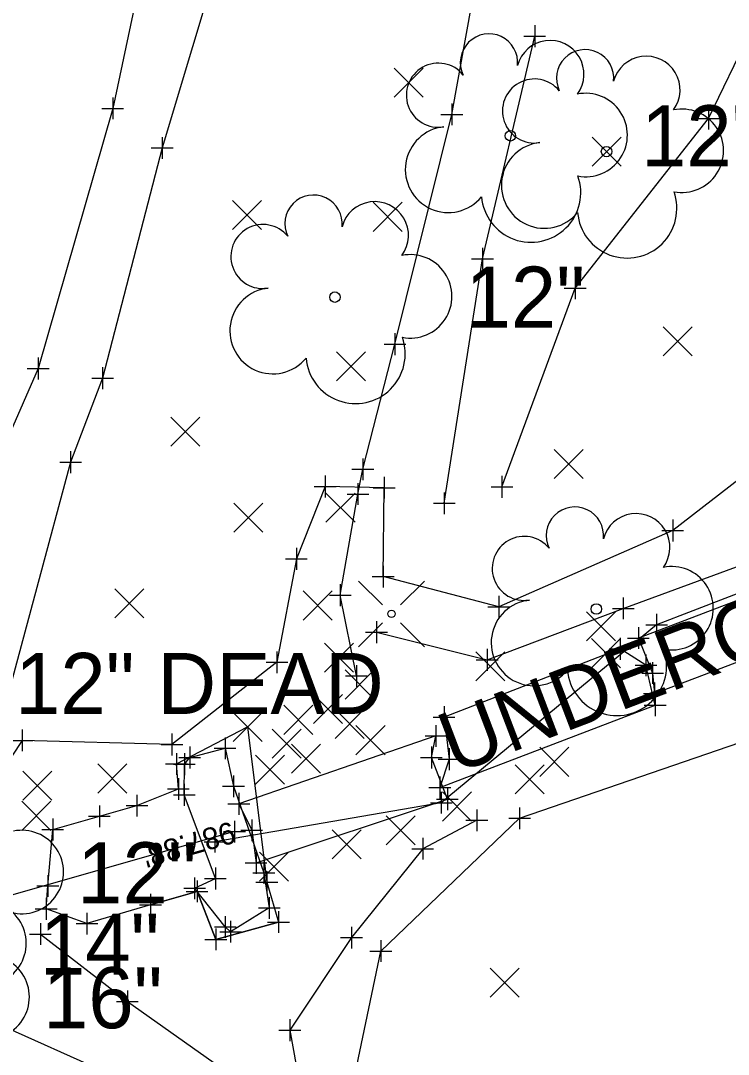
# Model space of a CAD drawing. Extents: x 160138 to 160780, y 488720 to 491073.
# Drawn here: x 160554.44 to 160586.95, y 489677.72 to 489725.18 of the extents above; entities that cross this region are included whole.
import ezdxf

# ---------------------------------------------------------------- set-up
doc = ezdxf.new("R2010")
doc.units = 0
for name, color, linetype in [('_CIVIL_CONSTRUCTION', 7, 'Continuous'), ('DR_X_Storm_Sewer', 7, 'Continuous'), ('GE_X_Alignment_500_Distances', 7, 'Continuous'), ('RD_X_Concrete_Pad', 7, 'Continuous'), ('RD_X_Text', 7, 'Continuous'), ('RS_Raster1', 7, 'Continuous'), ('RW_X_CL_100_Bearings', 7, 'Continuous'), ('RW_X_CL_100_Stations', 7, 'Continuous'), ('SC_Scratch1', 7, 'Continuous'), ('SV_P_Control_Cells_Set', 7, 'Continuous'), ('SV_P_Mon_Cells_Set', 7, 'Continuous'), ('SV_X_Mon_Cells_Found', 7, 'Continuous'), ('SV_X_Random_Point', 7, 'Continuous'), ('VG_X_Text', 7, 'Continuous')]:
    doc.layers.add(name, color=color, linetype=linetype)

msp = doc.modelspace()

# ---------------------------------------------------------------- linework, layer by layer
at = {"layer": '_CIVIL_CONSTRUCTION'}
for p, q in [((160571.607, 489721.667), (160572.94, 489723.002)), ((160571.607, 489723.002), (160572.94, 489721.667)), ((160580.689, 489718.502), (160582.022, 489719.837)), ((160580.689, 489719.837), (160582.022, 489718.502)), ((160564.175, 489715.593), (160565.509, 489716.928)), ((160564.175, 489716.928), (160565.509, 489715.593)), ((160570.633, 489715.508), (160571.967, 489716.843)), ((160570.633, 489716.843), (160571.967, 489715.508)), ((160583.953, 489709.785), (160585.287, 489711.12)), ((160583.953, 489711.12), (160585.287, 489709.785)), ((160568.958, 489708.644), (160570.292, 489709.979)), ((160568.958, 489709.979), (160570.292, 489708.644)), ((160561.347, 489705.64), (160562.68, 489706.975)), ((160561.347, 489706.975), (160562.68, 489705.64)), ((160578.954, 489704.16), (160580.287, 489705.495)), ((160578.954, 489705.495), (160580.287, 489704.16)), ((160568.47, 489702.149), (160569.804, 489703.484)), ((160568.47, 489703.484), (160569.804, 489702.149)), ((160564.232, 489701.7), (160565.566, 489703.035)), ((160564.232, 489703.035), (160565.566, 489701.7)), ((160558.775, 489697.757), (160560.109, 489699.092)), ((160558.775, 489699.092), (160560.109, 489697.757)), ((160567.424, 489697.663), (160568.758, 489698.998)), ((160567.424, 489698.998), (160568.758, 489697.663)), ((160580.437, 489696.706), (160581.77, 489698.041)), ((160580.437, 489698.041), (160581.77, 489696.706)), ((160568.408, 489695.263), (160569.741, 489696.598)), ((160568.408, 489696.598), (160569.741, 489695.263)), ((160580.664, 489695.471), (160581.997, 489696.807)), ((160580.664, 489696.807), (160581.997, 489695.471)), ((160575.353, 489694.863), (160576.686, 489696.198)), ((160575.353, 489696.198), (160576.686, 489694.863)), ((160569.356, 489694.034), (160570.689, 489695.369)), ((160569.356, 489695.369), (160570.689, 489694.034)), ((160567.902, 489692.913), (160569.235, 489694.248)), ((160567.902, 489694.248), (160569.235, 489692.913)), ((160566.54, 489692.413), (160567.873, 489693.748)), ((160566.54, 489693.748), (160567.873, 489692.413)), ((160564.203, 489692.088), (160565.536, 489693.423)), ((160564.203, 489693.423), (160565.536, 489692.088)), ((160568.886, 489692.23), (160570.219, 489693.565)), ((160568.886, 489693.565), (160570.219, 489692.23)), ((160569.848, 489691.48), (160571.182, 489692.815)), ((160569.848, 489692.815), (160571.182, 489691.48)), ((160565.998, 489691.321), (160567.331, 489692.656)), ((160565.998, 489692.656), (160567.331, 489691.321)), ((160566.884, 489690.626), (160568.218, 489691.961)), ((160566.884, 489691.961), (160568.218, 489690.626)), ((160578.298, 489690.483), (160579.632, 489691.818)), ((160578.298, 489691.818), (160579.632, 489690.483)), ((160565.225, 489690.126), (160566.558, 489691.461)), ((160565.225, 489691.461), (160566.558, 489690.126)), ((160557.983, 489689.717), (160559.316, 489691.052)), ((160557.983, 489691.052), (160559.316, 489689.717)), ((160577.158, 489689.68), (160578.491, 489691.015)), ((160577.158, 489691.015), (160578.491, 489689.68)), ((160554.544, 489689.387), (160555.877, 489690.722)), ((160554.544, 489690.722), (160555.877, 489689.387)), ((160573.818, 489688.432), (160575.152, 489689.767)), ((160573.818, 489689.767), (160575.152, 489688.432)), ((160554.491, 489688.003), (160555.824, 489689.338)), ((160554.491, 489689.338), (160555.824, 489688.003)), ((160571.232, 489687.339), (160572.565, 489688.674)), ((160571.232, 489688.674), (160572.565, 489687.339)), ((160568.755, 489686.697), (160570.089, 489688.032)), ((160568.755, 489688.032), (160570.089, 489686.697)), ((160565.413, 489685.676), (160566.746, 489687.011)), ((160565.413, 489687.011), (160566.746, 489685.676)), ((160576.007, 489680.345), (160577.34, 489681.68)), ((160576.007, 489681.68), (160577.34, 489680.345))]:
    msp.add_line(p, q, dxfattribs=at)
at = {"layer": 'DR_X_Storm_Sewer'}
msp.add_line((160564.265, 489687.947), (160487.37, 489666.011), dxfattribs=at)
at = {"layer": 'GE_X_Alignment_500_Distances'}
for points in [[(160621.534, 489717.15), (160606.181, 489710.759), (160597.835, 489707.435), (160587.92, 489704.491), (160584.396, 489701.774), (160576.406, 489698.274), (160571.095, 489699.657), (160571.143, 489703.736), (160568.43, 489703.792), (160567.108, 489700.473), (160566.216, 489695.724), (160561.396, 489691.947), (160554.509, 489692.134), (160553.007, 489689.884), (160552.633, 489686.649), (160552.379, 489683.318), (160552.332, 489681.352), (160553.749, 489678.967), (160558.048, 489677.046), (160562.424, 489674.113), (160566.368, 489663.913), (160565.537, 489659.127), (160562.724, 489647.863)], [(160567.306, 489654.928), (160569.133, 489661.115), (160570.764, 489664.778), (160569.567, 489671.947), (160569.755, 489676.53), (160570.988, 489682.463), (160577.363, 489688.561), (160592.024, 489693.602), (160606.811, 489697.077), (160621.483, 489700.054)]]:
    msp.add_lwpolyline(points, dxfattribs=at)
at = {"layer": 'RD_X_Concrete_Pad'}
for points in [[(160592.827, 489697.813), (160592.353, 489699.297), (160591.743, 489700.234), (160582.82, 489696.835), (160583.474, 489695.225), (160583.555, 489694.287)], [(160583.592, 489693.755), (160583.169, 489695.583), (160581.979, 489696.34), (160573.892, 489693.209), (160574.124, 489691.273), (160573.701, 489689.972)], [(160574.046, 489689.436), (160573.313, 489691.352), (160573.522, 489692.342), (160564.464, 489689.222), (160565.057, 489688.007), (160565.255, 489686.51)]]:
    msp.add_lwpolyline(points, close=True, dxfattribs=at)
at = {"layer": 'RS_Raster1'}
for p, q in [((160564.265, 489688.447), (160564.265, 489687.447)), ((160563.765, 489687.947), (160564.765, 489687.947)), ((160564.265, 489687.947), (160564.265, 489687.947))]:
    msp.add_line(p, q, dxfattribs=at)
at = {"layer": 'RW_X_CL_100_Bearings'}
msp.add_lwpolyline([(160561.962, 489689.638), (160561.964, 489691.045), (160562.212, 489691.351), (160563.831, 489691.775), (160564.22, 489690.031), (160565.616, 489686.052), (160565.866, 489684.442), (160564.087, 489683.349), (160563.844, 489683.569), (160562.436, 489685.346), (160563.388, 489685.794)], close=True, dxfattribs=at)
at = {"layer": 'RW_X_CL_100_Stations'}
msp.add_lwpolyline([(160565.751, 489685.631), (160566.286, 489683.792), (160563.41, 489683.001), (160562.546, 489685.202), (160560.409, 489684.584), (160557.488, 489683.722), (160555.616, 489684.401), (160555.694, 489685.452), (160555.919, 489688.046), (160558.059, 489688.651), (160559.787, 489689.139), (160561.689, 489689.907), (160561.603, 489691.053), (160564.87, 489692.755)], close=True, dxfattribs=at)
at = {"layer": 'SC_Scratch1'}
for centre in [(160576.941, 489719.895), (160581.356, 489719.17), (160568.88, 489712.488), (160580.887, 489698.167)]:
    msp.add_circle(centre, 0.24, dxfattribs=at)
for centre, radius, start, end in [((160575.957, 489723.262), 1.317, 354.0047, 205.9741), ((160578.767, 489722.724), 1.553, 323.83, 165.0376), ((160580.372, 489722.537), 1.317, 354.0047, 205.9741), ((160573.632, 489721.759), 1.471, 39.0625, 279.5412), ((160583.182, 489721.999), 1.553, 323.83, 165.0376), ((160578.046, 489721.034), 1.471, 39.0625, 279.5412), ((160580.401, 489719.931), 1.915, 259.1453, 101.4596), ((160584.816, 489719.206), 1.915, 259.1453, 101.4596), ((160574.088, 489718.346), 1.974, 96.1722, 320.5737), ((160578.502, 489717.621), 1.974, 96.1722, 320.5737), ((160577.888, 489717.289), 2.284, 184.9476, 19.4572), ((160567.897, 489715.856), 1.317, 354.0047, 205.9741), ((160582.302, 489716.565), 2.284, 184.9476, 19.4572), ((160570.707, 489715.318), 1.553, 323.83, 165.0376), ((160565.571, 489714.353), 1.471, 39.0625, 279.5412), ((160572.341, 489712.524), 1.915, 259.1453, 101.4596), ((160566.027, 489710.94), 1.974, 96.1722, 320.5737), ((160569.827, 489709.883), 2.284, 184.9476, 19.4572), ((160579.903, 489701.535), 1.317, 354.0047, 205.9741), ((160582.713, 489700.996), 1.553, 323.83, 165.0376), ((160577.577, 489700.031), 1.471, 39.0625, 279.5412), ((160584.347, 489698.203), 1.915, 259.1453, 101.4596), ((160578.033, 489696.618), 1.974, 96.1722, 320.5737), ((160581.833, 489695.562), 2.284, 184.9476, 19.4572), ((160554.499, 489686.092), 1.915, 259.1453, 101.4596), ((160552.789, 489682.822), 1.915, 259.1453, 101.4596), ((160552.931, 489680.354), 1.915, 259.1453, 101.4596)]:
    msp.add_arc(centre, radius, start, end, dxfattribs=at)
at = {"layer": 'SV_P_Control_Cells_Set'}
for points in [[(160565.084, 489733.119), (160560.945, 489719.34), (160558.207, 489708.768), (160556.738, 489704.911), (160553.646, 489693.395)], [(160560.406, 489729.318), (160558.674, 489721.152), (160555.249, 489709.209), (160553.876, 489706.065), (160550.231, 489693.069), (160550.251, 489690.788)], [(160576.55, 489703.778), (160579.917, 489712.897), (160586.034, 489720.686), (160589.811, 489728.475)], [(160573.904, 489703.024), (160575.658, 489714.25), (160578.057, 489724.469)], [(160570.792, 489697.104), (160575.871, 489695.835), (160582.126, 489698.194), (160589.99, 489701.077), (160597.61, 489703.891), (160611.482, 489708.49), (160617.773, 489711.561), (160624.019, 489713.541), (160631.981, 489716.744), (160639.194, 489717.897), (160645.106, 489719.665)], [(160561.603, 489691.053), (160564.87, 489692.755), (160565.751, 489685.631), (160565.751, 489685.631)], [(160575.398, 489688.469), (160572.912, 489687.162), (160569.643, 489683.078), (160566.808, 489678.832), (160568.176, 489671.267), (160568.821, 489664.576)], [(160560.409, 489684.584), (160562.546, 489685.202), (160563.41, 489683.001), (160566.286, 489683.792)], [(160555.352, 489683.246), (160559.345, 489680.149), (160563.956, 489676.888), (160566.188, 489671.679), (160567.307, 489663.814), (160566.9, 489660.613)]]:
    msp.add_lwpolyline(points, dxfattribs=at)
at = {"layer": 'SV_P_Mon_Cells_Set'}
for points in [[(160569.866, 489695.093), (160569.128, 489698.804), (160569.935, 489703.448), (160570.16, 489704.582), (160571.639, 489710.329), (160574.249, 489720.877), (160576.789, 489734.924), (160578.98, 489743.661)], [(160642.298, 489714.198), (160635.133, 489713.639), (160628.549, 489712.85), (160610.996, 489707.492), (160597, 489702.59), (160583.659, 489697.445), (160573.764, 489689.275), (160563.368, 489687.484)]]:
    msp.add_lwpolyline(points, dxfattribs=at)
at = {"layer": 'SV_X_Mon_Cells_Found'}
for p, q in [((160569.97, 489699.453), (160571.064, 489698.359)), ((160571.897, 489698.359), (160572.989, 489699.453)), ((160569.97, 489696.434), (160571.064, 489697.528)), ((160571.897, 489697.528), (160572.989, 489696.434))]:
    msp.add_line(p, q, dxfattribs=at)
msp.add_circle((160571.48, 489697.949), 0.17, dxfattribs=at)
at = {"layer": 'SV_X_Random_Point'}
for p, q in [((160578.057, 489724.969), (160578.057, 489723.969)), ((160577.557, 489724.469), (160578.557, 489724.469)), ((160578.057, 489724.469), (160578.057, 489724.469)), ((160558.674, 489721.652), (160558.674, 489720.652)), ((160574.249, 489721.377), (160574.249, 489720.377)), ((160558.174, 489721.152), (160559.174, 489721.152)), ((160558.674, 489721.152), (160558.674, 489721.152)), ((160573.749, 489720.877), (160574.749, 489720.877)), ((160574.249, 489720.877), (160574.249, 489720.877)), ((160586.034, 489721.186), (160586.034, 489720.186)), ((160585.534, 489720.686), (160586.534, 489720.686)), ((160586.034, 489720.686), (160586.034, 489720.686)), ((160560.945, 489719.84), (160560.945, 489718.84)), ((160560.445, 489719.34), (160561.445, 489719.34)), ((160560.945, 489719.34), (160560.945, 489719.34)), ((160575.658, 489714.75), (160575.658, 489713.75)), ((160575.158, 489714.25), (160576.158, 489714.25)), ((160575.658, 489714.25), (160575.658, 489714.25)), ((160579.917, 489713.397), (160579.917, 489712.397)), ((160579.417, 489712.897), (160580.417, 489712.897)), ((160579.917, 489712.897), (160579.917, 489712.897)), ((160571.639, 489710.829), (160571.639, 489709.829)), ((160571.139, 489710.329), (160572.139, 489710.329)), ((160571.639, 489710.329), (160571.639, 489710.329)), ((160555.249, 489709.709), (160555.249, 489708.709)), ((160554.749, 489709.209), (160555.749, 489709.209)), ((160555.249, 489709.209), (160555.249, 489709.209)), ((160558.207, 489709.268), (160558.207, 489708.268)), ((160557.707, 489708.768), (160558.707, 489708.768)), ((160558.207, 489708.768), (160558.207, 489708.768)), ((160556.738, 489705.411), (160556.738, 489704.411)), ((160556.238, 489704.911), (160557.238, 489704.911)), ((160556.738, 489704.911), (160556.738, 489704.911)), ((160570.16, 489705.082), (160570.16, 489704.082)), ((160568.43, 489704.292), (160568.43, 489703.292)), ((160569.66, 489704.582), (160570.66, 489704.582)), ((160570.16, 489704.582), (160570.16, 489704.582)), ((160571.143, 489704.236), (160571.143, 489703.236)), ((160576.55, 489704.278), (160576.55, 489703.278)), ((160567.93, 489703.792), (160568.93, 489703.792)), ((160568.43, 489703.792), (160568.43, 489703.792)), ((160569.935, 489703.948), (160569.935, 489702.948)), ((160570.643, 489703.736), (160571.643, 489703.736)), ((160571.143, 489703.736), (160571.143, 489703.736)), ((160576.05, 489703.778), (160577.05, 489703.778)), ((160576.55, 489703.778), (160576.55, 489703.778)), ((160569.435, 489703.448), (160570.435, 489703.448)), ((160569.935, 489703.448), (160569.935, 489703.448)), ((160573.904, 489703.524), (160573.904, 489702.524)), ((160573.404, 489703.024), (160574.404, 489703.024)), ((160573.904, 489703.024), (160573.904, 489703.024)), ((160584.396, 489702.274), (160584.396, 489701.274)), ((160583.896, 489701.774), (160584.896, 489701.774)), ((160584.396, 489701.774), (160584.396, 489701.774)), ((160567.108, 489700.973), (160567.108, 489699.973)), ((160566.608, 489700.473), (160567.608, 489700.473)), ((160567.108, 489700.473), (160567.108, 489700.473)), ((160571.095, 489700.157), (160571.095, 489699.157)), ((160570.595, 489699.657), (160571.595, 489699.657)), ((160571.095, 489699.657), (160571.095, 489699.657)), ((160569.128, 489699.304), (160569.128, 489698.304)), ((160568.628, 489698.804), (160569.628, 489698.804)), ((160569.128, 489698.804), (160569.128, 489698.804)), ((160576.406, 489698.774), (160576.406, 489697.774)), ((160582.126, 489698.694), (160582.126, 489697.694)), ((160575.906, 489698.274), (160576.906, 489698.274)), ((160576.406, 489698.274), (160576.406, 489698.274)), ((160581.626, 489698.194), (160582.626, 489698.194)), ((160582.126, 489698.194), (160582.126, 489698.194)), ((160570.792, 489697.604), (160570.792, 489696.604)), ((160583.659, 489697.945), (160583.659, 489696.945)), ((160570.292, 489697.104), (160571.292, 489697.104)), ((160570.792, 489697.104), (160570.792, 489697.104)), ((160582.82, 489697.335), (160582.82, 489696.335)), ((160583.159, 489697.445), (160584.159, 489697.445)), ((160583.659, 489697.445), (160583.659, 489697.445)), ((160581.979, 489696.84), (160581.979, 489695.84)), ((160582.32, 489696.835), (160583.32, 489696.835)), ((160582.82, 489696.835), (160582.82, 489696.835)), ((160566.216, 489696.224), (160566.216, 489695.224)), ((160575.871, 489696.335), (160575.871, 489695.335)), ((160581.479, 489696.34), (160582.479, 489696.34)), ((160581.979, 489696.34), (160581.979, 489696.34)), ((160583.169, 489696.083), (160583.169, 489695.083)), ((160565.716, 489695.724), (160566.716, 489695.724)), ((160566.216, 489695.724), (160566.216, 489695.724)), ((160575.371, 489695.835), (160576.371, 489695.835)), ((160575.871, 489695.835), (160575.871, 489695.835)), ((160583.474, 489695.725), (160583.474, 489694.725)), ((160569.866, 489695.593), (160569.866, 489694.593)), ((160582.669, 489695.583), (160583.669, 489695.583)), ((160582.974, 489695.225), (160583.974, 489695.225)), ((160583.169, 489695.583), (160583.169, 489695.583)), ((160583.474, 489695.225), (160583.474, 489695.225)), ((160569.366, 489695.093), (160570.366, 489695.093)), ((160569.866, 489695.093), (160569.866, 489695.093)), ((160583.555, 489694.787), (160583.555, 489693.787)), ((160583.055, 489694.287), (160584.055, 489694.287)), ((160583.555, 489694.287), (160583.555, 489694.287)), ((160583.592, 489694.255), (160583.592, 489693.255)), ((160573.892, 489693.709), (160573.892, 489692.709)), ((160583.092, 489693.755), (160584.092, 489693.755)), ((160583.592, 489693.755), (160583.592, 489693.755)), ((160573.392, 489693.209), (160574.392, 489693.209)), ((160573.522, 489692.842), (160573.522, 489691.842)), ((160573.892, 489693.209), (160573.892, 489693.209)), ((160554.509, 489692.634), (160554.509, 489691.634)), ((160561.396, 489692.447), (160561.396, 489691.447)), ((160573.022, 489692.342), (160574.022, 489692.342)), ((160573.522, 489692.342), (160573.522, 489692.342)), ((160554.009, 489692.134), (160555.009, 489692.134)), ((160554.509, 489692.134), (160554.509, 489692.134)), ((160560.896, 489691.947), (160561.896, 489691.947)), ((160561.396, 489691.947), (160561.396, 489691.947)), ((160562.212, 489691.851), (160562.212, 489690.851)), ((160563.831, 489692.275), (160563.831, 489691.275)), ((160573.313, 489691.852), (160573.313, 489690.852)), ((160561.603, 489691.553), (160561.603, 489690.553)), ((160561.712, 489691.351), (160562.712, 489691.351)), ((160561.964, 489691.545), (160561.964, 489690.545)), ((160562.212, 489691.351), (160562.212, 489691.351)), ((160563.331, 489691.775), (160564.331, 489691.775)), ((160563.831, 489691.775), (160563.831, 489691.775)), ((160572.813, 489691.352), (160573.813, 489691.352)), ((160573.313, 489691.352), (160573.313, 489691.352)), ((160574.124, 489691.773), (160574.124, 489690.773)), ((160561.103, 489691.053), (160562.103, 489691.053)), ((160561.464, 489691.045), (160562.464, 489691.045)), ((160561.603, 489691.053), (160561.603, 489691.053)), ((160561.964, 489691.045), (160561.964, 489691.045)), ((160573.624, 489691.273), (160574.624, 489691.273)), ((160574.124, 489691.273), (160574.124, 489691.273)), ((160561.689, 489690.407), (160561.689, 489689.407)), ((160564.22, 489690.531), (160564.22, 489689.531)), ((160573.701, 489690.472), (160573.701, 489689.472)), ((160561.962, 489690.138), (160561.962, 489689.138)), ((160563.72, 489690.031), (160564.72, 489690.031)), ((160564.22, 489690.031), (160564.22, 489690.031)), ((160573.201, 489689.972), (160574.201, 489689.972)), ((160573.701, 489689.972), (160573.701, 489689.972)), ((160574.046, 489689.936), (160574.046, 489688.936)), ((160559.787, 489689.639), (160559.787, 489688.639)), ((160561.189, 489689.907), (160562.189, 489689.907)), ((160561.462, 489689.638), (160562.462, 489689.638)), ((160561.689, 489689.907), (160561.689, 489689.907)), ((160561.962, 489689.638), (160561.962, 489689.638)), ((160564.464, 489689.722), (160564.464, 489688.722)), ((160573.546, 489689.436), (160574.546, 489689.436)), ((160573.764, 489689.775), (160573.764, 489688.775)), ((160574.046, 489689.436), (160574.046, 489689.436)), ((160558.059, 489689.151), (160558.059, 489688.151)), ((160559.287, 489689.139), (160560.287, 489689.139)), ((160559.787, 489689.139), (160559.787, 489689.139)), ((160563.964, 489689.222), (160564.964, 489689.222)), ((160564.464, 489689.222), (160564.464, 489689.222)), ((160573.264, 489689.275), (160574.264, 489689.275)), ((160573.764, 489689.275), (160573.764, 489689.275)), ((160575.398, 489688.969), (160575.398, 489687.969)), ((160577.363, 489689.061), (160577.363, 489688.061)), ((160555.919, 489688.546), (160555.919, 489687.546)), ((160557.559, 489688.651), (160558.559, 489688.651)), ((160558.059, 489688.651), (160558.059, 489688.651)), ((160565.057, 489688.507), (160565.057, 489687.507)), ((160576.863, 489688.561), (160577.863, 489688.561)), ((160577.363, 489688.561), (160577.363, 489688.561)), ((160555.419, 489688.046), (160556.419, 489688.046)), ((160555.919, 489688.046), (160555.919, 489688.046)), ((160574.898, 489688.469), (160575.898, 489688.469)), ((160575.398, 489688.469), (160575.398, 489688.469)), ((160563.368, 489687.984), (160563.368, 489686.984)), ((160564.557, 489688.007), (160565.557, 489688.007)), ((160565.057, 489688.007), (160565.057, 489688.007)), ((160572.912, 489687.662), (160572.912, 489686.662)), ((160562.868, 489687.484), (160563.868, 489687.484)), ((160563.368, 489687.484), (160563.368, 489687.484)), ((160572.412, 489687.162), (160573.412, 489687.162)), ((160572.912, 489687.162), (160572.912, 489687.162)), ((160565.255, 489687.01), (160565.255, 489686.01)), ((160563.388, 489686.294), (160563.388, 489685.294)), ((160564.755, 489686.51), (160565.755, 489686.51)), ((160565.255, 489686.51), (160565.255, 489686.51)), ((160565.616, 489686.552), (160565.616, 489685.552)), ((160565.751, 489686.131), (160565.751, 489685.131)), ((160555.694, 489685.952), (160555.694, 489684.952)), ((160562.436, 489685.846), (160562.436, 489684.846)), ((160562.546, 489685.702), (160562.546, 489684.702)), ((160562.888, 489685.794), (160563.888, 489685.794)), ((160563.388, 489685.794), (160563.388, 489685.794)), ((160565.116, 489686.052), (160566.116, 489686.052)), ((160565.616, 489686.052), (160565.616, 489686.052)), ((160555.194, 489685.452), (160556.194, 489685.452)), ((160555.694, 489685.452), (160555.694, 489685.452)), ((160561.936, 489685.346), (160562.936, 489685.346)), ((160562.046, 489685.202), (160563.046, 489685.202)), ((160562.436, 489685.346), (160562.436, 489685.346)), ((160562.546, 489685.202), (160562.546, 489685.202)), ((160565.251, 489685.631), (160566.251, 489685.631)), ((160565.751, 489685.631), (160565.751, 489685.631)), ((160555.616, 489684.901), (160555.616, 489683.901)), ((160560.409, 489685.084), (160560.409, 489684.084)), ((160565.866, 489684.942), (160565.866, 489683.942)), ((160555.116, 489684.401), (160556.116, 489684.401)), ((160555.616, 489684.401), (160555.616, 489684.401)), ((160557.488, 489684.222), (160557.488, 489683.222)), ((160559.909, 489684.584), (160560.909, 489684.584)), ((160560.409, 489684.584), (160560.409, 489684.584)), ((160565.366, 489684.442), (160566.366, 489684.442)), ((160565.866, 489684.442), (160565.866, 489684.442)), ((160566.286, 489684.292), (160566.286, 489683.292)), ((160555.352, 489683.746), (160555.352, 489682.746)), ((160563.844, 489684.069), (160563.844, 489683.069)), ((160564.087, 489683.849), (160564.087, 489682.849)), ((160565.786, 489683.792), (160566.786, 489683.792)), ((160566.286, 489683.792), (160566.286, 489683.792)), ((160556.988, 489683.722), (160557.988, 489683.722)), ((160557.488, 489683.722), (160557.488, 489683.722)), ((160563.344, 489683.569), (160564.344, 489683.569)), ((160563.41, 489683.501), (160563.41, 489682.501)), ((160563.587, 489683.349), (160564.587, 489683.349)), ((160563.844, 489683.569), (160563.844, 489683.569)), ((160564.087, 489683.349), (160564.087, 489683.349)), ((160569.643, 489683.578), (160569.643, 489682.578)), ((160554.852, 489683.246), (160555.852, 489683.246)), ((160555.352, 489683.246), (160555.352, 489683.246)), ((160562.91, 489683.001), (160563.91, 489683.001)), ((160563.41, 489683.001), (160563.41, 489683.001)), ((160569.143, 489683.078), (160570.143, 489683.078)), ((160569.643, 489683.078), (160569.643, 489683.078)), ((160570.988, 489682.963), (160570.988, 489681.963)), ((160570.488, 489682.463), (160571.488, 489682.463)), ((160570.988, 489682.463), (160570.988, 489682.463)), ((160559.345, 489680.649), (160559.345, 489679.649)), ((160558.845, 489680.149), (160559.845, 489680.149)), ((160559.345, 489680.149), (160559.345, 489680.149)), ((160566.808, 489679.332), (160566.808, 489678.332)), ((160566.308, 489678.832), (160567.308, 489678.832)), ((160566.808, 489678.832), (160566.808, 489678.832))]:
    msp.add_line(p, q, dxfattribs=at)

# ---------------------------------------------------------------- texts
at = {"layer": 'RD_X_Text'}
msp.add_text("UNDERCUT CONCRETE TROUGH'S", height=2.8, rotation=20.8489, dxfattribs=at).set_placement((160574.362, 489690.574))
at = {"layer": 'SC_Scratch1'}
msp.add_text("987.88'", height=1, rotation=195.9216, dxfattribs=at).set_placement((160564.128, 489688.428))
at = {"layer": 'VG_X_Text'}
for s, p in [('12"', (160582.941, 489718.495)), ('12"', (160574.88, 489711.089)), ('12" DEAD', (160554.186, 489693.351)), ('12"', (160557.039, 489684.656)), ('14"', (160555.328, 489681.386)), ('16"', (160555.47, 489678.918))]:
    msp.add_text(s, height=2.8, dxfattribs=at).set_placement(p)

doc.saveas('drawing.dxf')
